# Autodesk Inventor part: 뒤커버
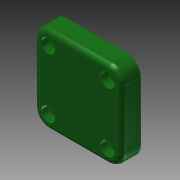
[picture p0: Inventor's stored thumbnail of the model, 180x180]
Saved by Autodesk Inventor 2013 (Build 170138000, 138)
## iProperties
Created: 2018-07
Part Number: 뒤커버
Material: 알루미늄 6061
Document SubType Name: Modeling
Designer: mduedu
Density: 1 g/cm^3
Author: mduedu
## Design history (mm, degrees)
sketch "스케치1"
  geometry: C1 r 16 at (0, 0); 1 further point
  constraints: 1 centre point, 1 coincident
  dimensions: "d0" = 32 diameter of C1
extrude "돌출1" new body sketch "스케치1" distance "d1" = 3; taper "d2" = 0 deg
sketch "스케치2"
  geometry: L1 (-25, -25)-(25, -25); L2 (25, -25)-(25, 25); L3 (25, 25)-(-25, 25); L4 (-25, 25)-(-25, -25); L5 (-25, -25)-(25, 25); L6 (25, -25)-(-25, 25); 1 further point
  constraints: 12 end point, 2 midpoint, 2 parallel, 1 horizontal, 1 perpendicular
  dimensions: "d3" = 50 distance of L3.end L2.end; "d4" = 50 distance of L2.end L1.end
extrude "돌출2" join sketch "스케치2" distance "d5" = 11; taper "d6" = 0 deg
hole "구멍1" diameter "d9" = 25; stored, may be unused: countersink angle "d13" = 90 deg, drill point angle "d15" = 0 deg; dims "d7" = 10, "d8" = 10, "d10" = 6, "d11" = 4, "d12" = 2, "d14" = 3
fillet "모깎기2" dims "d26" = 3
fillet "모깎기3" dims "d27" = 8
sketch "스케치5"
  geometry: L1 (25, -17)-(25, 17) reference; L2 (17, 25)-(-17, 25) reference; L3 (-25, 17)-(-25, -17) reference; L4 (-17, -25)-(17, -25) reference; A1 r 8 centre (17, -17) between (17, -25) and (25, -17) reference; A2 r 8 centre (17, 17) between (25, 17) and (17, 25) reference; A3 r 8 centre (-17, 17) between (-17, 25) and (-25, 17) reference; A4 r 8 centre (-17, -17) between (-25, -17) and (-17, -25) reference; 5 further points
  constraints: 4 coincident
hole "구멍2" sketch "스케치5" at (-17, 17), (17, 17), (17, -17), (-17, -17) diameter "d28" = 4.5; stored, may be unused: countersink angle "d32" = 90 deg, drill point angle "d34" = 0 deg; dims "d29" = 6, "d30" = 8, "d31" = 4.6, "d33" = 3
fillet "모깎기4" dims "d35" = 3
chamfer "모따기2" distance "d36" = 1; stored, may be unused: second distance "d37" = 2, angle "d38" = 45 deg
node "솔리드1"
node "투영된 루프1"
